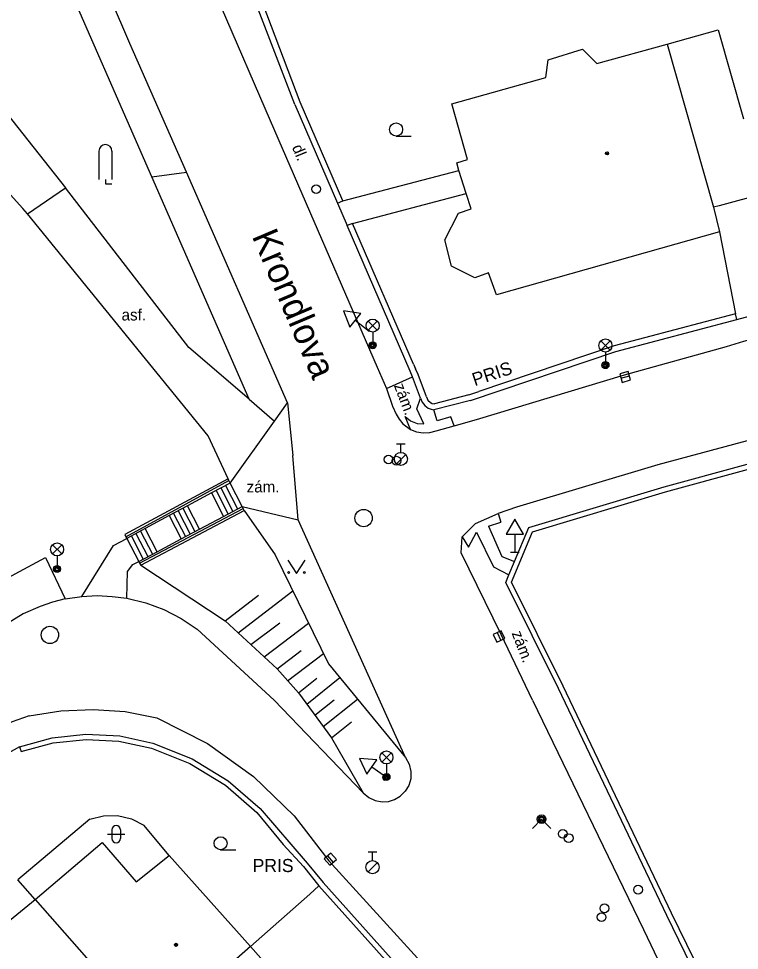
# Model space of a CAD drawing. Extents: x -600391 to -599491, y -1160176 to -1159402.
# Drawn here: x -600119.6 to -600078.3, y -1159526.5 to -1159473.1 of the extents above; entities that cross this region are included whole.
import ezdxf

# ---------------------------------------------------------------- set-up
doc = ezdxf.new("R2010")
doc.units = 0
for name, color, linetype in [('Level 10', 7, 'Continuous'), ('Level 11', 7, 'Continuous'), ('Level 14', 7, 'Continuous'), ('Level 15', 7, 'Continuous'), ('Level 27', 7, 'Continuous'), ('Level 28', 7, 'Continuous'), ('Level 31', 7, 'Continuous'), ('Level 33', 7, 'Continuous'), ('Level 34', 7, 'Continuous'), ('Level 36', 7, 'Continuous'), ('Level 39', 7, 'Continuous'), ('Level 40', 7, 'Continuous'), ('Level 41', 7, 'Continuous'), ('Level 5', 7, 'Continuous'), ('Level 50', 7, 'Continuous'), ('Level 7', 7, 'Continuous'), ('Level 8', 7, 'Continuous'), ('Level 9', 7, 'Continuous')]:
    doc.layers.add(name, color=color, linetype=linetype)

msp = doc.modelspace()

# ---------------------------------------------------------------- linework, layer by layer
at = {"layer": 'Level 10'}
for points in [[(-600104.2, -1159495.08), (-600110.003, -1159481.864), (-600113.25, -1159474.47), (-600120.19, -1159458.3), (-600129.62, -1159437.69), (-600134.22, -1159427.17), (-600140.79, -1159413.72), (-600147.219, -1159401.769)], [(-600141.674, -1159401.769), (-600140.112, -1159404.661), (-600136.38, -1159411.57), (-600135.242, -1159413.89), (-600133.488, -1159417.464), (-600131.149, -1159422.23), (-600129.991, -1159424.591), (-600129.53, -1159425.53), (-600124.09, -1159437.21), (-600121.712, -1159442.301), (-600119.452, -1159447.141), (-600119.06, -1159447.98), (-600114.1, -1159458.57), (-600109.124, -1159469.878), (-600108.01, -1159472.4), (-600105.198, -1159478.889), (-600099.063, -1159493.031), (-600098.53, -1159494.26)], [(-600079.03, -1159491.85), (-600078.03, -1159491.54), (-600074.6, -1159490.61), (-600073.59, -1159490.35), (-600069.44, -1159489.2), (-600068.42, -1159488.89), (-600065.59, -1159488.13), (-600064.01, -1159487.71), (-600063.04, -1159487.45), (-600053.67, -1159485.22), (-600045.6, -1159483.41), (-600032.42, -1159480.93)], [(-600030.14, -1159486.13), (-600039.7, -1159487.93), (-600044.49, -1159488.82), (-600059.39, -1159492.23), (-600067.1, -1159494.38), (-600082.96, -1159498.64), (-600091.07, -1159501.07)], [(-600094.65, -1159496.4), (-600093.36, -1159496.03), (-600084.88, -1159493.48), (-600079.03, -1159491.85)], [(-600098.53, -1159494.26), (-600098.18, -1159495.27)], [(-600104.2, -1159495.08), (-600103.9, -1159498.1)], [(-600098.18, -1159495.27), (-600097.98, -1159495.73)], [(-600097.98, -1159495.73), (-600097.81, -1159496.02), (-600097.6, -1159496.28), (-600097.15, -1159496.62)], [(-600097.15, -1159496.62), (-600096.8, -1159496.75), (-600096.43, -1159496.81), (-600096.04, -1159496.79), (-600095.67, -1159496.69)], [(-600095.67, -1159496.69), (-600094.65, -1159496.4)], [(-600103.59, -1159501.8), (-600103.9, -1159498.1)], [(-600091.07, -1159501.07), (-600092.12, -1159501.43)], [(-600094.18, -1159502.76), (-600093.42, -1159502.01), (-600092.12, -1159501.43)], [(-600097.44, -1159515.42), (-600103.59, -1159501.8)], [(-600094.25, -1159503.68), (-600094.18, -1159502.76)], [(-600090.16, -1159512.14), (-600091.95, -1159508.37), (-600094.25, -1159503.68)], [(-600116.96, -1159506.33), (-600117.68, -1159506.52), (-600118.39, -1159506.76), (-600119.36, -1159507.19), (-600120.27, -1159507.73)], [(-600116.96, -1159506.33), (-600116, -1159506.19)], [(-600116, -1159506.19), (-600115.13, -1159506.14), (-600114.27, -1159506.18), (-600113.41, -1159506.29), (-600112.33, -1159506.55), (-600111.29, -1159506.94), (-600110.3, -1159507.45), (-600109.38, -1159508.07)], [(-600109.38, -1159508.07), (-600104.97, -1159512.14), (-600099.86, -1159517.45)], [(-600090.16, -1159512.14), (-600083.79, -1159525.29), (-600079.03, -1159535.25)], [(-600119.02, -1159513.04), (-600117.2, -1159512.74), (-600115.35, -1159512.66), (-600113.51, -1159512.79), (-600111.69, -1159513.14), (-600108.8, -1159514.62), (-600106.16, -1159516.51), (-600103.82, -1159518.77), (-600101.84, -1159521.34)], [(-600119.02, -1159513.04), (-600120, -1159513.38), (-600122.59, -1159514.72), (-600123.48, -1159515.21)], [(-600097.44, -1159515.42), (-600097.23, -1159515.8), (-600097.13, -1159516.22), (-600097.14, -1159516.65), (-600097.25, -1159517.03), (-600097.46, -1159517.36), (-600097.74, -1159517.64)], [(-600099.86, -1159517.45), (-600099.55, -1159517.71), (-600099.18, -1159517.89), (-600098.78, -1159517.96), (-600098.41, -1159517.94), (-600098.06, -1159517.83), (-600097.74, -1159517.64)], [(-600101.84, -1159521.34), (-600093.02, -1159531.02)]]:
    msp.add_lwpolyline(points, dxfattribs=at)
at = {"layer": 'Level 11'}
for points in [[(-600173.816, -1159401.769), (-600198.35, -1159458.02), (-600178.76, -1159455.83), (-600159.15, -1159457.83), (-600153.36, -1159459.27), (-600140.92, -1159463.74), (-600127.94, -1159471.21), (-600124.01, -1159474.44), (-600121.85, -1159476.56), (-600116.94, -1159482.75)], [(-600106.4, -1159494.88), (-600111.984, -1159482.12), (-600117.51, -1159469.49), (-600125.45, -1159451.57), (-600142.57, -1159414.45), (-600149.556, -1159401.769)], [(-600119.38, -1159483.93), (-600124.15, -1159478.68), (-600129.2, -1159473.68), (-600142.96, -1159465.32), (-600154.3, -1159461.38)], [(-600082.44, -1159474.51), (-600079.78, -1159483.87)], [(-600111.984, -1159482.12), (-600110.003, -1159481.864)], [(-600101.03, -1159483.5), (-600094.37, -1159481.75)], [(-600119.117, -1159484.253), (-600116.94, -1159482.75)], [(-600106.4, -1159494.88), (-600109.87, -1159491.9), (-600116.94, -1159482.75)], [(-600100.48, -1159484.79), (-600093.95, -1159483.08)], [(-600107.61, -1159499.45), (-600108.76, -1159496.97), (-600119.117, -1159484.253), (-600119.38, -1159483.93)], [(-600079.43, -1159485.28), (-600078.52, -1159489.97)], [(-600098.53, -1159494.26), (-600097.03, -1159493.59)], [(-600106.4, -1159494.88), (-600104.95, -1159496.13)], [(-600104.95, -1159496.13), (-600104.2, -1159495.08)], [(-600096.38, -1159496.28), (-600096.79, -1159495.42), (-600096.57, -1159494.81)], [(-600094.65, -1159496.4), (-600094.84, -1159495.88), (-600095.62, -1159496.12), (-600095.81, -1159495.48)], [(-600107.5, -1159499.68), (-600104.95, -1159496.13)], [(-600097.46, -1159495.86), (-600097.15, -1159496.12), (-600096.77, -1159496.26), (-600096.38, -1159496.28)], [(-600097.15, -1159496.62), (-600097.46, -1159495.86)], [(-600108.29, -1159500.11), (-600107.6, -1159501.46)], [(-600108.03, -1159499.96), (-600107.34, -1159501.32)], [(-600107.77, -1159499.82), (-600107.07, -1159501.17)], [(-600106.8, -1159501.03), (-600107.5, -1159499.68)], [(-600108.56, -1159500.249), (-600107.871, -1159501.598)], [(-600110.21, -1159501.13), (-600109.52, -1159502.47)], [(-600109.258, -1159502.334), (-600109.94, -1159500.99)], [(-600106.8, -1159501.03), (-600103.59, -1159501.8)], [(-600110.99, -1159501.55), (-600110.297, -1159502.885)], [(-600110.74, -1159501.42), (-600110.05, -1159502.75)], [(-600110.47, -1159501.28), (-600109.78, -1159502.61)], [(-600092.12, -1159501.43), (-600091.97, -1159501.93)], [(-600092.67, -1159502.16), (-600091.97, -1159501.93)], [(-600092.67, -1159502.16), (-600091.91, -1159503.89)], [(-600113.16, -1159502.72), (-600112.48, -1159504.04)], [(-600112.9, -1159502.58), (-600112.21, -1159503.9)], [(-600112.64, -1159502.44), (-600111.95, -1159503.76)], [(-600111.685, -1159503.62), (-600112.37, -1159502.29)], [(-600094.18, -1159502.76), (-600093.83, -1159503.35)], [(-600093.83, -1159503.35), (-600093.37, -1159502.49)], [(-600093.37, -1159502.49), (-600092.4, -1159504.48), (-600091.51, -1159504.95)], [(-600116, -1159506.19), (-600114.19, -1159503.26), (-600113.42, -1159502.86)], [(-600113.42, -1159502.86), (-600112.74, -1159504.18)], [(-600155.12, -1159524.03), (-600137.91, -1159514.34), (-600124.74, -1159507.52), (-600118.08, -1159503.96), (-600116.96, -1159506.33)], [(-600113.41, -1159506.29), (-600113.39, -1159504.75), (-600113.08, -1159504.36), (-600112.74, -1159504.18)], [(-600091.91, -1159503.89), (-600091.19, -1159504.19)], [(-600115.55, -1159518.95), (-600114.76, -1159518.76), (-600113.96, -1159518.75), (-600113.16, -1159518.94), (-600112.44, -1159519.3)], [(-600115.55, -1159518.95), (-600119.67, -1159522.44)], [(-600110.99, -1159521.04), (-600112.44, -1159519.3)]]:
    msp.add_lwpolyline(points, dxfattribs=at)
at = {"layer": 'Level 14'}
for points in [[(-600106.69, -1159501.25), (-600104.91, -1159503.79)], [(-600104.91, -1159503.79), (-600101.86, -1159510.04), (-600097.44, -1159515.42)], [(-600112.62, -1159504.4), (-600107.78, -1159507.58), (-600104.8, -1159510.34), (-600103.58, -1159511.71), (-600101.68, -1159514.29), (-600099.86, -1159517.45)]]:
    msp.add_lwpolyline(points, dxfattribs=at)
at = {"layer": 'Level 15'}
for points in [[(-600107.04, -1159508.27), (-600103.9, -1159505.87)], [(-600107.78, -1159507.58), (-600105.86, -1159506.11)], [(-600106.3, -1159508.95), (-600104.65, -1159507.7)], [(-600105.55, -1159509.64), (-600103, -1159507.71)], [(-600104.8, -1159510.34), (-600103.43, -1159509.29)], [(-600104.2, -1159511.02), (-600102.14, -1159509.46)], [(-600103.58, -1159511.71), (-600102.53, -1159510.87)], [(-600103.1, -1159512.36), (-600101.2, -1159510.84)], [(-600102.63, -1159513), (-600101.53, -1159512.12)], [(-600102.16, -1159513.64), (-600100.19, -1159512.07)], [(-600101.68, -1159514.29), (-600100.53, -1159513.37)]]:
    msp.add_lwpolyline(points, dxfattribs=at)
at = {"layer": 'Level 27'}
for p, q in [((-600085.081, -1159493.668), (-600084.599, -1159493.532)), ((-600092.175, -1159508.253), (-600091.965, -1159508.707)), ((-600101.915, -1159521.062), (-600101.585, -1159521.438))]:
    msp.add_line(p, q, dxfattribs=at)
for points in [[(-600085.012, -1159493.909), (-600084.531, -1159493.772), (-600084.668, -1159493.291), (-600085.149, -1159493.428)], [(-600092.402, -1159508.358), (-600092.192, -1159508.812), (-600091.738, -1159508.602), (-600091.948, -1159508.148)], [(-600102.103, -1159521.227), (-600101.773, -1159521.603), (-600101.397, -1159521.273), (-600101.727, -1159520.897)]]:
    msp.add_lwpolyline(points, close=True, dxfattribs=at)
for centre in [(-600099.84, -1159501.69), (-600117.83, -1159508.39)]:
    msp.add_circle(centre, 0.5, dxfattribs=at)
at = {"layer": 'Level 28'}
for p, q in [((-600097.95, -1159497.425), (-600097.45, -1159497.425)), ((-600097.7, -1159497.925), (-600097.7, -1159497.425)), ((-600097.958, -1159498.572), (-600097.428, -1159498.042)), ((-600099.58, -1159520.835), (-600099.08, -1159520.835)), ((-600099.33, -1159521.335), (-600099.33, -1159520.835)), ((-600099.588, -1159521.982), (-600099.058, -1159521.452))]:
    msp.add_line(p, q, dxfattribs=at)
for centre, radius in [((-600102.56, -1159482.83), 0.25), ((-600097.7, -1159498.3), 0.375), ((-600098.41, -1159498.33), 0.25), ((-600097.96, -1159498.4), 0.25), ((-600088.42, -1159519.8), 0.25), ((-600088.08, -1159520.04), 0.25), ((-600099.33, -1159521.71), 0.375), ((-600084.1, -1159523), 0.25), ((-600086.03, -1159524.07), 0.25), ((-600086.19, -1159524.58), 0.25)]:
    msp.add_circle(centre, radius, dxfattribs=at)
at = {"layer": 'Level 31'}
msp.add_lwpolyline([(-600090.16, -1159519.49), (-600089.63, -1159518.96), (-600089.1, -1159519.49)], dxfattribs=at)
for radius in [0.25, 0.18, 0.11]:
    msp.add_circle((-600089.63, -1159518.96), radius, dxfattribs=at)
at = {"layer": 'Level 33'}
for p, q in [((-600099.585, -1159490.92), (-600099.055, -1159490.39)), ((-600099.585, -1159490.39), (-600099.055, -1159490.92)), ((-600099.32, -1159491.03), (-600099.32, -1159491.78)), ((-600086.235, -1159492.06), (-600085.705, -1159491.53)), ((-600086.235, -1159491.53), (-600085.705, -1159492.06)), ((-600085.97, -1159492.17), (-600085.97, -1159492.92)), ((-600117.685, -1159503.75), (-600117.155, -1159503.22)), ((-600117.685, -1159503.22), (-600117.155, -1159503.75)), ((-600117.42, -1159503.86), (-600117.42, -1159504.61)), ((-600098.795, -1159515.68), (-600098.265, -1159515.15)), ((-600098.795, -1159515.15), (-600098.265, -1159515.68)), ((-600098.53, -1159515.79), (-600098.53, -1159516.54))]:
    msp.add_line(p, q, dxfattribs=at)
for centre, radius in [((-600099.32, -1159490.655), 0.375), ((-600085.97, -1159491.795), 0.375), ((-600099.32, -1159491.78), 0.2), ((-600099.32, -1159491.78), 0.145), ((-600099.32, -1159491.78), 0.0876), ((-600085.97, -1159492.92), 0.2), ((-600085.97, -1159492.92), 0.145), ((-600085.97, -1159492.92), 0.0876), ((-600117.42, -1159503.485), 0.375), ((-600117.42, -1159504.61), 0.2), ((-600117.42, -1159504.61), 0.145), ((-600117.42, -1159504.61), 0.0876), ((-600098.53, -1159515.415), 0.375), ((-600098.53, -1159516.54), 0.2), ((-600098.53, -1159516.54), 0.145), ((-600098.53, -1159516.54), 0.0876)]:
    msp.add_circle(centre, radius, dxfattribs=at)
at = {"layer": 'Level 34'}
for p, q in [((-600100.318, -1159490.348), (-600099.52, -1159490.98)), ((-600091.17, -1159502.622), (-600091.17, -1159503.64)), ((-600091.42, -1159503.64), (-600090.92, -1159503.64)), ((-600099.369, -1159515.964), (-600098.53, -1159516.54)), ((-600098.671, -1159516.746), (-600098.389, -1159516.334))]:
    msp.add_line(p, q, dxfattribs=at)
for points in [[(-600100.629, -1159490.74), (-600100.008, -1159489.956), (-600100.997, -1159489.811)], [(-600091.67, -1159502.622), (-600090.67, -1159502.622), (-600091.17, -1159501.756)], [(-600099.652, -1159516.376), (-600099.086, -1159515.552), (-600100.083, -1159515.474)]]:
    msp.add_lwpolyline(points, close=True, dxfattribs=at)
at = {"layer": 'Level 36'}
for p, q in [((-600097.98, -1159479.785), (-600097.105, -1159479.785)), ((-600115.025, -1159480.645), (-600115.025, -1159482.27)), ((-600114.275, -1159480.645), (-600114.275, -1159482.27)), ((-600114.536, -1159519.816), (-600113.536, -1159519.816)), ((-600114.286, -1159519.566), (-600114.286, -1159520.066)), ((-600113.786, -1159519.566), (-600113.786, -1159520.066)), ((-600108.04, -1159520.715), (-600107.165, -1159520.715))]:
    msp.add_line(p, q, dxfattribs=at)
for points in [[(-600114.65, -1159482.27), (-600114.65, -1159482.52), (-600114.275, -1159482.52)], [(-600104.19, -1159504.11), (-600103.69, -1159504.86), (-600103.19, -1159504.11)]]:
    msp.add_lwpolyline(points, dxfattribs=at)
for centre, radius in [((-600097.98, -1159479.41), 0.375), ((-600104.14, -1159504.81), 0.05), ((-600103.241, -1159504.81), 0.05), ((-600108.04, -1159520.34), 0.375)]:
    msp.add_circle(centre, radius, dxfattribs=at)
for centre, radius, start, end in [((-600114.65, -1159480.645), 0.375, 0, 180), ((-600114.036, -1159519.566), 0.25, 0, 180), ((-600114.036, -1159520.066), 0.25, 180, 0)]:
    msp.add_arc(centre, radius, start, end, dxfattribs=at)
at = {"layer": 'Level 39'}
for centre, radius in [((-600085.88, -1159480.78), 0.09), ((-600085.88, -1159480.78), 0.0398), ((-600110.6, -1159526.16), 0.09), ((-600110.6, -1159526.16), 0.0398)]:
    msp.add_circle(centre, radius, dxfattribs=at)
at = {"layer": 'Level 5'}
for points in [[(-600082.44, -1159474.51), (-600079.5, -1159473.7)], [(-600079.5, -1159473.7), (-600078.06, -1159478.8)], [(-600089.26, -1159475.42), (-600087.28, -1159474.8)], [(-600087.28, -1159474.8), (-600086.47, -1159475.63)], [(-600086.47, -1159475.63), (-600082.44, -1159474.51)], [(-600089.38, -1159476.43), (-600089.26, -1159475.42)], [(-600094.78, -1159477.93), (-600089.38, -1159476.43)], [(-600093.88, -1159481.13), (-600094.78, -1159477.93)], [(-600094.5, -1159481.32), (-600093.88, -1159481.13)], [(-600093.68, -1159483.96), (-600093.95, -1159483.08), (-600094.37, -1159481.75), (-600094.5, -1159481.32)], [(-600076.85, -1159483.08), (-600079.44, -1159483.78)], [(-600094.4, -1159484.21), (-600093.68, -1159483.96)], [(-600079.44, -1159483.78), (-600079.78, -1159483.87)], [(-600079.78, -1159483.87), (-600079.43, -1159485.28)], [(-600095.19, -1159485.73), (-600094.4, -1159484.21)], [(-600079.43, -1159485.28), (-600092.21, -1159488.88)], [(-600094.8, -1159487.24), (-600095.19, -1159485.73)], [(-600093.47, -1159487.91), (-600094.8, -1159487.24)], [(-600092.67, -1159487.62), (-600093.47, -1159487.91)], [(-600092.21, -1159488.88), (-600092.67, -1159487.62)], [(-600118.68, -1159523.57), (-600114.83, -1159520.29)], [(-600114.83, -1159520.29), (-600112.88, -1159522.55)], [(-600112.88, -1159522.55), (-600110.99, -1159521.04)], [(-600110.99, -1159521.04), (-600106.32, -1159526.25)], [(-600122.78, -1159526.9), (-600118.68, -1159523.57)], [(-600118.68, -1159523.57), (-600111.95, -1159531.2)], [(-600106.32, -1159526.25), (-600111.95, -1159531.2)], [(-600106.32, -1159526.25), (-600096.47, -1159537.4)]]:
    msp.add_lwpolyline(points, dxfattribs=at)
at = {"layer": 'Level 7'}
for points in [[(-600103.78, -1159477.98), (-600106.07, -1159472.01)], [(-600101.34, -1159483.64), (-600101.03, -1159483.5), (-600103.47, -1159477.85), (-600105.61, -1159472.25)], [(-600103.78, -1159477.98), (-600101.34, -1159483.64)], [(-600100.48, -1159484.79), (-600100.79, -1159484.92)], [(-600097.17, -1159493.27), (-600100.79, -1159484.92)], [(-600096.98, -1159492.86), (-600100.48, -1159484.79)], [(-600093.71, -1159494.94), (-600085.37, -1159492.14), (-600078.43, -1159490.3)], [(-600078.43, -1159490.3), (-600078.52, -1159489.97), (-600085.47, -1159491.82), (-600093.23, -1159494.44)], [(-600096.98, -1159492.86), (-600096.86, -1159493.13)], [(-600096.24, -1159494.74), (-600096.72, -1159493.46), (-600096.86, -1159493.13)], [(-600097.03, -1159493.59), (-600097.17, -1159493.27)], [(-600096.57, -1159494.81), (-600097.03, -1159493.59)], [(-600096.24, -1159494.74), (-600096.16, -1159494.93), (-600096.01, -1159495.07), (-600095.9, -1159495.12), (-600095.78, -1159495.14)], [(-600093.81, -1159494.62), (-600095.78, -1159495.14)], [(-600093.81, -1159494.62), (-600093.23, -1159494.44)], [(-600096.57, -1159494.81), (-600096.48, -1159495.04), (-600096.33, -1159495.24), (-600096.13, -1159495.39), (-600095.97, -1159495.45), (-600095.81, -1159495.48)], [(-600093.71, -1159494.94), (-600095.81, -1159495.48)], [(-600091.19, -1159504.19), (-600090.37, -1159502.23), (-600082.61, -1159499.9), (-600069.17, -1159496.23)], [(-600091.36, -1159505.37), (-600090.15, -1159502.48), (-600082.53, -1159500.19), (-600069.09, -1159496.52)], [(-600107.61, -1159499.45), (-600113.54, -1159502.64), (-600113.47, -1159502.76)], [(-600107.57, -1159499.53), (-600107.61, -1159499.45)], [(-600107.5, -1159499.68), (-600107.57, -1159499.53)], [(-600107.5, -1159499.68), (-600108.56, -1159500.249), (-600109.94, -1159500.99), (-600110.99, -1159501.55), (-600112.37, -1159502.29), (-600113.42, -1159502.86)], [(-600112.74, -1159504.18), (-600111.685, -1159503.62), (-600110.297, -1159502.885), (-600109.258, -1159502.334), (-600107.871, -1159501.598), (-600106.8, -1159501.03)], [(-600106.75, -1159501.14), (-600106.8, -1159501.03)], [(-600106.69, -1159501.25), (-600106.75, -1159501.14)], [(-600112.62, -1159504.4), (-600106.69, -1159501.25)], [(-600113.47, -1159502.76), (-600113.42, -1159502.86)], [(-600112.74, -1159504.18), (-600112.69, -1159504.27)], [(-600112.69, -1159504.27), (-600112.62, -1159504.4)], [(-600091.51, -1159504.95), (-600091.19, -1159504.19)], [(-600091.69, -1159505.38), (-600091.51, -1159504.95)], [(-600078.97, -1159531.62), (-600082.45, -1159524.48), (-600088.66, -1159511.46), (-600091.69, -1159505.38)], [(-600078.67, -1159531.54), (-600082.18, -1159524.35), (-600088.39, -1159511.33), (-600091.36, -1159505.37)], [(-600119.58, -1159514.8), (-600117.7, -1159514.29), (-600115.77, -1159514.08), (-600113.82, -1159514.18), (-600111.92, -1159514.59), (-600109.67, -1159515.49), (-600107.61, -1159516.75), (-600105.78, -1159518.34), (-600103.07, -1159521.48)], [(-600119.58, -1159514.8), (-600117.7, -1159514.29), (-600115.77, -1159514.08), (-600113.82, -1159514.18), (-600111.92, -1159514.59), (-600109.67, -1159515.49), (-600107.61, -1159516.75), (-600105.78, -1159518.34), (-600103.07, -1159521.48)], [(-600119.58, -1159514.8), (-600119.48, -1159515.08), (-600117.65, -1159514.58), (-600115.76, -1159514.38), (-600113.87, -1159514.48), (-600112.01, -1159514.88), (-600109.8, -1159515.77), (-600107.77, -1159517.01), (-600105.97, -1159518.57), (-600104.46, -1159520.41)], [(-600119.58, -1159514.8), (-600119.48, -1159515.08), (-600117.65, -1159514.58), (-600115.76, -1159514.38), (-600113.87, -1159514.48), (-600112.01, -1159514.88), (-600109.8, -1159515.77), (-600107.77, -1159517.01), (-600105.97, -1159518.57), (-600104.46, -1159520.41)], [(-600104.46, -1159520.41), (-600103.29, -1159521.68)], [(-600103.07, -1159521.48), (-600102.16, -1159522.58)], [(-600103.29, -1159521.68), (-600102.4, -1159522.77)], [(-600118.68, -1159523.57), (-600119.67, -1159522.44)], [(-600102.4, -1159522.77), (-600102.92, -1159523.25), (-600106.32, -1159526.25)], [(-600102.4, -1159522.77), (-600092.81, -1159533.49)], [(-600102.16, -1159522.58), (-600092.59, -1159533.29)]]:
    msp.add_lwpolyline(points, dxfattribs=at)
at = {"layer": 'Level 8'}
for points in [[(-600101.34, -1159483.64), (-600100.79, -1159484.92)], [(-600078.43, -1159490.3), (-600075.03, -1159489.38)], [(-600119.58, -1159514.8), (-600121.69, -1159516)]]:
    msp.add_lwpolyline(points, dxfattribs=at)
at = {"layer": 'Level 9'}
for points in [[(-600113.47, -1159502.76), (-600107.57, -1159499.53)], [(-600112.69, -1159504.27), (-600106.75, -1159501.14)]]:
    msp.add_lwpolyline(points, dxfattribs=at)

# ---------------------------------------------------------------- texts
at = {"layer": 'Level 40'}
for s, rotation, p in [('dl.', 292.26, (-600103.96, -1159480.42)), ('zám.', 290.83, (-600098.11, -1159494.09)), ('zám.', 291.13, (-600091.36, -1159508.29))]:
    msp.add_text(s, height=0.65, rotation=rotation, dxfattribs=at).set_placement(p)
for s, p in [('asf.', (-600113.72, -1159490.36)), ('zám.', (-600106.55, -1159500.22))]:
    msp.add_text(s, height=0.65, dxfattribs=at).set_placement(p)
at = {"layer": 'Level 41'}
msp.add_text('PRIS', height=0.75, rotation=18.2, dxfattribs=at).set_placement((-600093.47, -1159494.13))
msp.add_text('PRIS', height=0.75, dxfattribs=at).set_placement((-600106.2, -1159521.99))
msp.add_text('PRIS', height=0.75, dxfattribs=at).set_placement((-600106.2, -1159521.99))
at = {"layer": 'Level 50'}
msp.add_text('Krondlova', height=1.5, rotation=292.9722, dxfattribs=at).set_placement((-600106.267, -1159485.518))

doc.saveas('drawing.dxf')
